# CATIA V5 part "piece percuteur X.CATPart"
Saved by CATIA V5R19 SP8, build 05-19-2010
Part number: pièce percuteur X
Bounding box of the stored display mesh (mm): x 0 to 14, y -3.978 to 3.978, z -3.83 to 3.501
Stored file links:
  C:\Users\Arthur\Desktop\Catia parts\GLOCK\Ensemble culasse\piece percuteur X.CATPart
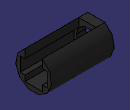
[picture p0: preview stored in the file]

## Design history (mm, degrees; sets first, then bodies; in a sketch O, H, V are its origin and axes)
Set1
  Sketch1 on yz-plane, origin (0, 0, 0), H (0, 1, 0), V (0, 0, 1)
    axis line L1 (20, 6) -> (-20, 6)
    line L2 (-1.935, 3.5008) -> (1.935, 3.5008)
    point P3 (-1.935, 3.5008)
    point P4 (1.935, 3.5008)
    arc A1 centre (0, 0) radius 4 from (-1.935, 3.5008) to (1.935, 3.5008) ccw
    distance L1 H = 6
    radius A1 = 4
    distance P4 P3 = 3.87
    horizontal: L1 H, L2 H
    symmetry: P4 P3 V
Body1 (main body)
  Pad1: profile Sketch1, direction (1, 0, 0), length 14
  Sketch2 on end face of Pad1, origin (14, 0, 0), H (0, 1, 0), V (0, 0, 1)
    axis line L1 (20, 6) -> (-20, 6)
    line L2 (-1.935, 3.5008) -> (1.935, 3.5008)
    point P3 (-1.935, 3.5008)
    point P4 (1.935, 3.5008)
    arc A1 centre (0, 0) radius 4 from (-1.935, 3.5008) to (1.935, 3.5008) ccw
    distance L1 H = 6
    radius A1 = 4
    distance P4 P3 = 3.87
    horizontal: L1 H, L2 H
    symmetry: P4 P3 V
  Sketch3 on yz-plane, origin (0, 0, 0), H (0, 1, 0), V (0, 0, 1)
    axis line L1 (0, 10) -> (0, -10)
    circle A1 centre (0, 0) radius 2.5
    point P3 (0, 0)
    radius A1 = 2.5
    vertical: L1 V
    coincidence: L1 V, P3 L1, P3 O
  Pocket1: profile Sketch3, direction (1, 0, 0), length 22
  Sketch4 on end face of Pad1, origin (14, 0, 0), H (0, 1, 0), V (0, 0, 1)
    line L1 (-1.935, 3.5008) -> (-1.935, 1.583)
    point P1 (-1.935, 3.5008)
    line L2 (-1.935, 3.5008) -> (1.935, 3.5008)
    point P3 (1.935, 3.5008)
    line L3 (1.935, 3.5008) -> (1.935, 1.583)
    point P4 (1.935, 1.583)
    line L4 (1.935, 1.583) -> (3, 1.583)
    line L5 (-1.935, 1.583) -> (-3, 1.583)
    line L6 (3, 1.583) -> (3, -1.583)
    line L7 (-3, 1.583) -> (-3, -1.583)
    line L8 (-3, -1.583) -> (-1.935, -1.583)
    point P9 (-1.935, -1.583)
    line L9 (-1.935, -1.583) -> (-1.935, -2.833)
    line L10 (-1.935, -2.833) -> (1.935, -2.833)
    line L11 (3, -1.583) -> (1.935, -1.583)
    line L12 (1.935, -2.833) -> (1.935, -1.583)
    reference projected circle E1 centre (0, 0) radius 2.5 from edge [end face of Pad1 | face of Pocket1 from Sketch3.A1]
    reference projected point E2 (1.935, 3.5008) from edge [face of Pad1 from Sketch1.L2 | face of Pad1 from Sketch1.A1]
    reference intersected line E3 (-1.935, 3.5008) -> (1.935, 3.5008) from face of Pad1 from Sketch1.L2
    reference projected point E4 (-1.935, 3.5008) from edge [face of Pad1 from Sketch1.A1 | face of Pad1 from Sketch1.L2]
    distance L6 L7 = 6
    distance L10 L8 = 1.25
    vertical: L1 V, L3 V, L6 V, L7 V, L9 V, L12 V
    horizontal: L2 H, L4 H, L5 H, L8 H, L10 H, L11 H
    coincidence: L5 L4, P9 L1, L11 L8, P4 E1, P3 E2, L2 E3, P1 E4
    symmetry: L6 L7 V, L12 L9 V, L11 L4 H
  Pocket2: profile Sketch4, direction (-1, 0, 0), length 12
  Pad2: profile Sketch2, direction (1, 0, 0), length 14
Current feature: Pocket2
